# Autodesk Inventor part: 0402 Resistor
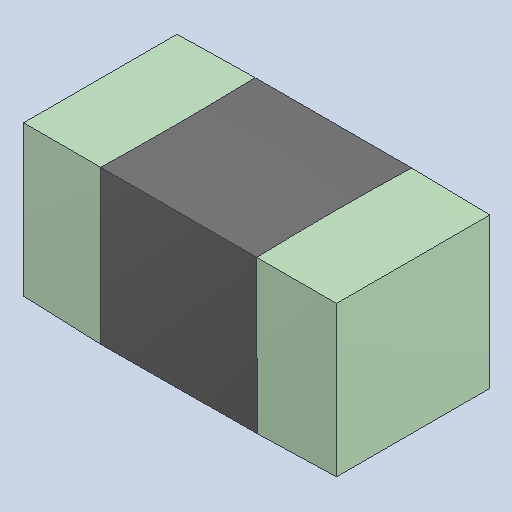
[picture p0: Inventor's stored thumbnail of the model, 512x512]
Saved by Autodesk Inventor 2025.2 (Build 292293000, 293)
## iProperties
Created: 2025-04
Part Number: 0402 Resistor
Material: Generic
Description: PART--DESC
Document SubType Name: Modeling
Designer: BennF
Density: 1 g/cm^3
Appearance: Default
Author: BennF
Revision Number: NONE
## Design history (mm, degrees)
feature "Solid1"
body "Solid2"
